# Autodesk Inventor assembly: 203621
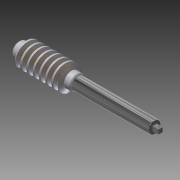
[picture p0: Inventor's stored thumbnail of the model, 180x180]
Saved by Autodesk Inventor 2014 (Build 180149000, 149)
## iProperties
Created: 2008-01
Part Number: 203621
Document SubType Name: Assembly
Designer: jjohnson
Mass: 26.128 g
Surface Area: 46.9717 cm^2
Volume: 6.69373 cm^3
Density: 3.90335 g/cm^3
Author: jjohnson
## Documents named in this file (3)
- C:\Users\iTools\Desktop\tutorial files\Automotive\2000\203621.iam
- C:\Users\iTools\Desktop\tutorial files\Automotive\2000\201077.ipt
- C:\Users\iTools\Desktop\tutorial files\Automotive\2000\200910.ipt
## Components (2 placed, 2 different names)
1. 201077:1 — Insert:1
2. Worm:1 — Insert:1
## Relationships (1: Insert 1)
- Insert:1: 201077:1 ↔ Worm:1
